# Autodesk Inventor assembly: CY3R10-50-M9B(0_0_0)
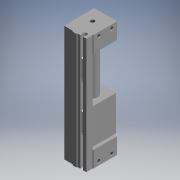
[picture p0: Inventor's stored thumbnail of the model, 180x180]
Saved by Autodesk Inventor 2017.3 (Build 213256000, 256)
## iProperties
Category: PARTsolutions
Company: SMC
Part Number: CY3R10-50-M9B(0_0_0)
Catalog Web Link: www.cadenas.de
Description: CY3R-Magnetically Coupled Rodless Cylinder Direct Mount Type
Vendor: SMC
Document SubType Name: Assembly
Designer: partserver
Manufacturer: SMC
Mass: 70.5141 g
Surface Area: 261.566 cm^2
Volume: 70.5141 cm^3
Density: 1 g/cm^3
Title: CY3R10-50-M9B
Author: Cadenas PARTsolutions
Comments: Magnetically Coupled Rodless Cylinder Direct Mount Type
PSOL_IDENT_0: {$CADENAS_DATA\23d-libs\smc_jp\actuator\rodless_cylinders\cy3\cy3r_asmtab.prj},266 {VTYP=3D},{STYP=A
PSOL_IDENT_1: SSTAB},{NB=CY3R10-50-M9B(0_0_0)},{LINA=CY3R10-50-M9B},{NN=CY3R},{DATE=12.02.2021 08:48:25},{GEOMDATE=
PSOL_IDENT_2: 14.07.2020 03:32:41},{VERSION=},{LINEID=20},{WBVAR=PIPING,THREAD1,STROKE,POS,STOP,RAIL,AUTOSWITCH,LE
PSOL_IDENT_3: AD,NUMBER,OMSC,THREAD2},{WBNUMERIC=STROKE,POS}  {NB=CY3R10-50-M9B(0_0_0)},{LINA=CY3R10-50-M9B},{KT=D
PSOL_IDENT_4: UMMY},{PIPING=},{PIPINGX='','(-) Standard type','G','(G) Centralized piping type'},{DI=1},{BORE=10},
PSOL_IDENT_5: {THREAD1=},{THREAD1X='','(-) M thread'},{STROKE=50},{STROKEX=50,100,150,200,250,300},{STDSTROKE=50,1
PSOL_IDENT_6: 00,150,200,250,300},{POS=0},{STOP=0},{COM=-},{RAIL=},{RALLX='', '(-) With switch rail', 'N', '(N) Wi
PSOL_IDENT_7: thout switch rail'},{AUTOSWITCH=-M9B},{AUTOSWITCHX='','(-) Without autoswitch (Built-in magnet)','-A
PSOL_IDENT_8: 90','A90','-A93','A93','-A96','A96','-M9N','M9N','-M9P','M9P','-M9B','M9B','-M9NW','M9NW','-M9PW','M
PSOL_IDENT_9: 9PW','-M9BW','M9BW','-M9NA','M9NA','-M9PA','M9PA','-M9BA','M9BA'},{LEAD=},{LEADX='','(-) 0.5 m','M','
PSOL_IDENT_10: (M) 1 m','L','(L) 3 m','Z','(Z) 5 m'},{NUMBER=},{NUMBERX='','(-) 2 Pcs','S','(S) 1 Pcs'},{OMSC=},{OM
PSOL_IDENT_11: SCX= '','(-) None','-XC57','(XC57) With floating joint'},{THREAD2=0},{SMIN1=25},{SMIN2=50},{SMAX1=50
PSOL_IDENT_12: 0},{SMAX2=500},{ORDER=CY3R10-50-M9B},{A=9.0},{B=6.5},{C=3.2},{CB=2},{CR=0.5},{D=12.0},{F=6.5},{G=4.0
PSOL_IDENT_13: },{GP=27},{GW=25.5},{H=26},{HA=24},{HB=14.0},{HC=25},{HP=14.0},{HP1=14.0},{HP2=0.0},{HR=24},{HS=5.0}
PSOL_IDENT_14: ,{HT=14.0},{HT1=14.0},{HT2=0.0},{JXE=M4x0.7x6},{K=9},{L=38},{LD=3.5},{M=4.0},{MM=M3x0.5},{N=4.5},{PW=
PSOL_IDENT_15: 26},{Q=68},{QW=14},{T=17.5},{TC=14.0},{W=20},{WP=13.0},{WS=8},{X=15},{Y=39.5},{Z=76},{P=M5x0.8},{PTN=
PSOL_IDENT_16: -},{PTF=-},{PPATH=cy3r/assembly/cy3r_asmsbl.prj},{MODEL=CY3R10-50-M9B},{NENN=CY3R10}
NB: CY3R10-50-M9B(0_0_0)
NN: CY3R
NT: Magnetically Coupled Rodless Cylinder Direct Mount Type
NBSYN: $ORDER.($POS._$STOP._$THREAD2.)
LINA: CY3R10-50-M9B
CATALOG: SMC (JP
ROWDESC: CY3R10
PIPING: (-) Standard type
BORE: 10
THREAD1: (-) M thread
STROKE: 50
POS: 0
STOP: Standard stroke
COM: -
RAIL: (-) With switch rail
AUTOSWITCH: M9B Solid state-General-Grommet-Indicator light:Yes-2 wire-In line
LEAD: (-) 0.5 m
NUMBER: (-) 2 Pcs
OMSC: (-) None
THREAD2: on
SUPPLIER: SMC
ARTICLENO: CY3R10-50-M9B(0_0_0)
BOMINFO: CY3R10-50-M9B
CREATOR: CADENAS GmbH
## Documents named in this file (4)
- e:\temp\worker_3\temp\exporttempdir_304_161_BExde\format_0\CY3R10-50-M9B(0_0_0).iam
- e:\temp\worker_3\temp\exporttempdir_304_161_BExde\format_0\CY3R10-50-M9B(0)_CT.ipt
- e:\temp\worker_3\temp\exporttempdir_304_161_BExde\format_0\CY3R10(0)_BODY.ipt
- e:\temp\worker_3\temp\exporttempdir_304_161_BExde\format_0\CY3R-M9B_SW.ipt
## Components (4 placed, 3 different names)
1. CY3R10-50-M9B(0)_CT:1
2. CY3R10(0)_BODY:1
3. CY3R-M9B_SW:1
4. CY3R-M9B_SW:2
